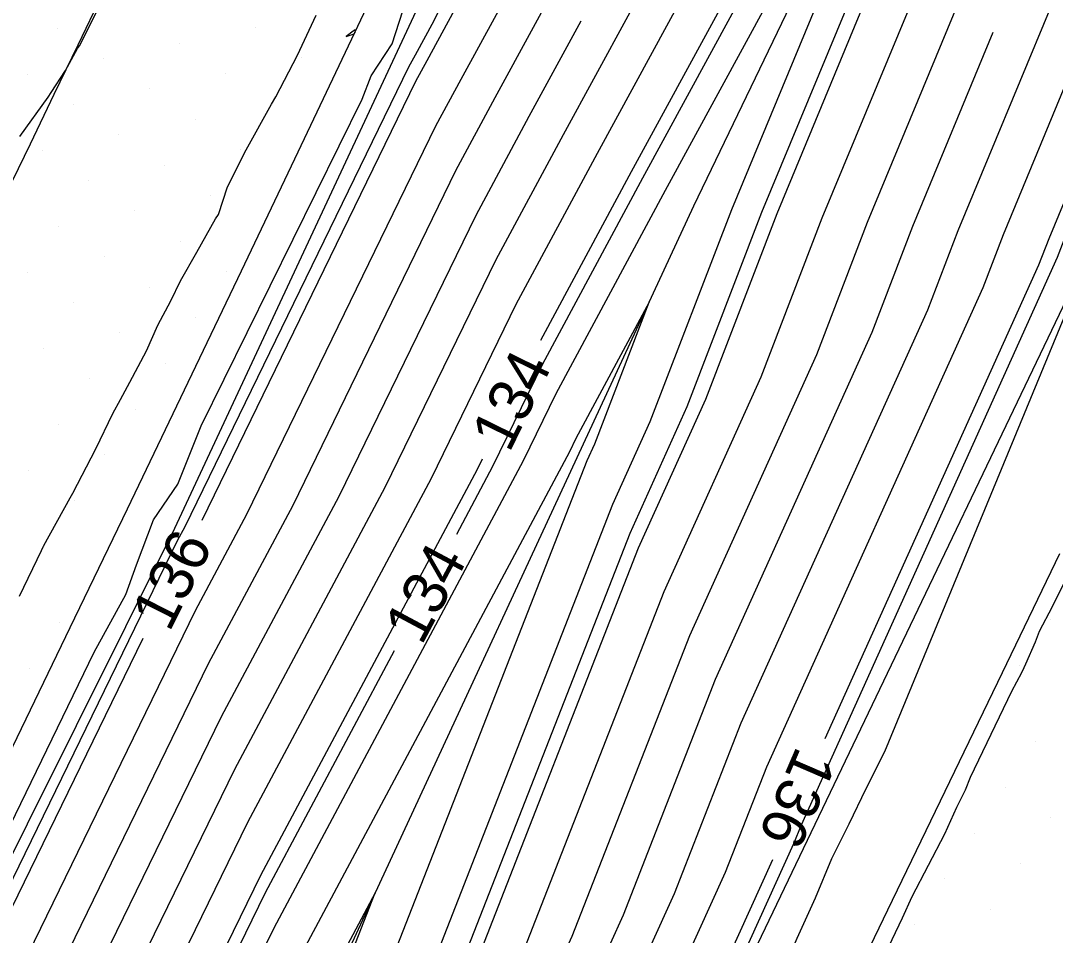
# Model space of a CAD drawing. Extents: x 2354170 to 2357230, y 866100 to 868290.
# Drawn here: x 2355291.7 to 2355338.78, y 866319.23 to 866360.82 of the extents above; entities that cross this region are included whole.
import ezdxf

# ---------------------------------------------------------------- set-up
doc = ezdxf.new("R2010")
doc.units = 0
for name, color, linetype in [('Default', 7, 'Continuous'), ('DTM Contours Major', 7, 'Continuous'), ('DTM Contours Minor', 7, 'Continuous'), ('DTM Contours Minor Text', 7, 'Continuous'), ('Exist DTM Breakline', 7, 'Continuous'), ('Exist DTM Scan Elevation Point', 7, 'Continuous'), ('Exist Roads EOP', 7, 'Continuous'), ('PH Exist DTM Breakline', 7, 'Continuous')]:
    doc.layers.add(name, color=color, linetype=linetype)

msp = doc.modelspace()

# ---------------------------------------------------------------- linework, layer by layer
at = {"layer": 'Default'}
for points in [[(2355362.019, 866434.7), (2355360.618, 866431.85), (2355360.1, 866430.777), (2355354.214, 866419.388), (2355353.064, 866417.142), (2355340.439, 866392.713), (2355339.805, 866391.476), (2355333.667, 866380.332), (2355331.988, 866376.904), (2355319.48, 866353.942), (2355315.349, 866346.27)], [(2355344.863, 866427.426), (2355333.508, 866405.265), (2355331.367, 866401.122), (2355324.415, 866387.55), (2355323.476, 866385.846), (2355311.639, 866361.675), (2355310.176, 866358.99), (2355309.668, 866358.047), (2355299.946, 866338.09)], [(2355346.547, 866426.331), (2355336.768, 866407.245), (2355332.879, 866399.721), (2355326.98, 866388.205), (2355325.175, 866384.927), (2355315.03, 866364.214), (2355311.726, 866358.149), (2355310.58, 866356.02), (2355301.98, 866338.364), (2355299.636, 866333.974), (2355288.647, 866311.443), (2355286.904, 866307.449), (2355279.659, 866292.572), (2355279.343, 866291.067), (2355277.379, 866286.427), (2355269.582, 866267.361)], [(2355370.996, 866418.563), (2355366.551, 866409.441), (2355365.482, 866407.418), (2355364.469, 866405.339), (2355362.138, 866400.926), (2355351.253, 866378.232), (2355350.488, 866376.361), (2355339.875, 866354.269), (2355338.477, 866350.901), (2355338.018, 866349.707), (2355328.291, 866328.165)], [(2355346.545, 866413.183), (2355337.415, 866395.516), (2355334.675, 866390.167), (2355330.27, 866382.17), (2355325.205, 866371.828), (2355316.378, 866355.625), (2355313.316, 866349.936), (2355308.274, 866339.587), (2355301.426, 866326.76), (2355294.428, 866312.41), (2355289.665, 866301.5), (2355285.05, 866292.025), (2355284.22, 866288.074), (2355279.066, 866275.895)], [(2355340.027, 866409.224), (2355334.391, 866398.319), (2355329.545, 866388.859), (2355326.873, 866384.008), (2355318.422, 866366.752), (2355313.277, 866357.307), (2355311.492, 866353.992), (2355304.078, 866338.772), (2355300.233, 866331.569), (2355290.574, 866311.765), (2355287.824, 866305.466), (2355281.456, 866292.39), (2355280.968, 866290.07), (2355277.941, 866282.916), (2355271.317, 866266.718)], [(2355338.927, 866394.115), (2355337.24, 866390.821), (2355331.969, 866381.251), (2355328.597, 866374.366), (2355317.929, 866354.783), (2355314.227, 866347.909), (2355310.373, 866339.995), (2355302.023, 866324.355), (2355296.354, 866312.732), (2355290.585, 866299.517), (2355286.848, 866291.842), (2355285.846, 866287.077), (2355279.628, 866272.384)], [(2355307.474, 866311.114), (2355309.825, 866316.293), (2355318.648, 866338.833), (2355320.345, 866342.59), (2355324.053, 866352.236), (2355335.221, 866379.152), (2355321.03, 866353.1), (2355316.051, 866343.853), (2355314.569, 866340.81), (2355303.217, 866319.546), (2355300.208, 866313.377), (2355292.425, 866295.55), (2355290.442, 866291.477), (2355289.097, 866285.082), (2355280.753, 866265.362)], [(2355295.93, 866277.918), (2355297.289, 866281.095), (2355299.682, 866284.596), (2355304.457, 866295.671), (2355310.044, 866308.469), (2355314.474, 866318.226), (2355320.982, 866334.853), (2355325.394, 866344.623), (2355328.175, 866351.855), (2355336.64, 866372.256), (2355339.663, 866378.549)], [(2355297.265, 866276.227), (2355299.022, 866280.337), (2355300.896, 866283.079), (2355306.792, 866296.752), (2355311.329, 866307.146), (2355316.798, 866319.192), (2355322.15, 866332.863), (2355327.919, 866345.64), (2355330.235, 866351.664), (2355337.287, 866368.659), (2355341.828, 866378.112)], [(2355299.933, 866272.846), (2355302.488, 866278.82), (2355303.324, 866280.044), (2355311.461, 866298.914), (2355313.9, 866304.5), (2355321.447, 866321.125), (2355324.484, 866328.882), (2355332.969, 866347.673), (2355334.356, 866351.282), (2355338.581, 866361.464), (2355346.158, 866377.236)], [(2355291.94, 866275.064), (2355294.596, 866279.608), (2355295.556, 866281.853), (2355298.468, 866286.114), (2355302.123, 866294.59), (2355308.759, 866309.791), (2355312.149, 866317.259), (2355319.815, 866336.843), (2355322.869, 866343.607), (2355326.114, 866352.046), (2355332.101, 866366.476)], [(2355291.664, 866355.545), (2355292.951, 866357.342), (2355293.092, 866357.551), (2355293.741, 866358.553), (2355294.287, 866359.562), (2355294.374, 866359.67), (2355295.392, 866361.693)], [(2355266.111, 866268.646), (2355275.282, 866291.07), (2355274.685, 866290.143), (2355275.184, 866291.11), (2355275.57, 866291.874), (2355275.855, 866292.514), (2355276.2, 866293.354), (2355276.747, 866294.675), (2355282.939, 866307.557), (2355283.875, 866309.403), (2355284.665, 866311.146), (2355285.537, 866312.659), (2355286.204, 866313.902), (2355295.041, 866332.108), (2355296.478, 866334.729), (2355296.966, 866336.075), (2355297.748, 866338.127), (2355298.85, 866339.748), (2355299.916, 866342.394), (2355307.241, 866357.243), (2355307.65, 866358.314), (2355308.598, 866359.764), (2355309.085, 866361.27)], [(2355317.189, 866360.801), (2355314.828, 866356.466), (2355312.404, 866351.964), (2355306.176, 866339.18), (2355300.829, 866329.165), (2355292.501, 866312.087), (2355288.744, 866303.483), (2355283.253, 866292.207), (2355282.594, 866289.072), (2355278.504, 866279.405), (2355274.815, 866270.385)], [(2355291.64, 866334.652), (2355292.651, 866336.721), (2355292.73, 866336.893), (2355292.744, 866336.919), (2355292.76, 866336.951), (2355293.956, 866339.114), (2355294.08, 866339.329), (2355295.117, 866341.344), (2355295.899, 866342.95), (2355296.24, 866343.598), (2355296.66, 866344.378), (2355297.427, 866345.811), (2355297.945, 866346.975), (2355298.537, 866348.074), (2355298.973, 866348.989), (2355299.722, 866350.288), (2355300.558, 866351.81), (2355300.697, 866352.008), (2355301.117, 866353.261), (2355301.965, 866354.951), (2355303.114, 866357.021), (2355303.307, 866357.358), (2355304.299, 866359.25), (2355305.15, 866361.071)], [(2355295.371, 866269.014), (2355298.599, 866274.537), (2355300.755, 866279.578), (2355302.11, 866281.561), (2355309.127, 866297.833), (2355312.615, 866305.823), (2355319.123, 866320.158), (2355323.317, 866330.872), (2355330.444, 866346.657), (2355332.296, 866351.473), (2355335.956, 866360.295)], [(2355306.914, 866360.278), (2355306.938, 866360.351), (2355306.918, 866360.404), (2355306.836, 866360.342), (2355306.514, 866360.095), (2355306.874, 866360.216), (2355306.914, 866360.278)], [(2355304.221, 866278.062), (2355304.538, 866278.526), (2355313.796, 866299.995), (2355315.185, 866303.177), (2355323.771, 866322.091), (2355325.651, 866326.892), (2355335.494, 866348.69), (2355336.417, 866351.091), (2355339.228, 866357.866)], [(2355340.495, 866350.531), (2355331.001, 866327.562), (2355330.154, 866325.881), (2355329.384, 866324.284), (2355328.592, 866322.7), (2355327.857, 866320.914), (2355327.02, 866319.083), (2355321.074, 866305.192), (2355319.633, 866302.589), (2355318.634, 866300.202), (2355317.41, 866297.966), (2355316.183, 866294.558), (2355312.238, 866284.632), (2355310.002, 866280.655), (2355308.5, 866277.295)], [(2355306.189, 866312.437), (2355307.5, 866315.326), (2355317.481, 866340.824), (2355317.82, 866341.573), (2355320.298, 866348.019), (2355316.963, 866341.825), (2355316.667, 866341.218), (2355303.813, 866317.142), (2355302.135, 866313.7), (2355293.346, 866293.567), (2355292.239, 866291.295), (2355290.723, 866284.084), (2355285.885, 866272.65), (2355291.928, 866282.99), (2355292.09, 866283.369), (2355296.039, 866289.149), (2355297.454, 866292.429), (2355306.189, 866312.437)], [(2355312.705, 866340.884), (2355312.471, 866340.403), (2355302.62, 866321.951), (2355298.281, 866313.055), (2355291.505, 866297.534), (2355288.645, 866291.66), (2355287.471, 866286.079), (2355280.19, 866268.873), (2355278.258, 866264.148), (2355277.348, 866261.759), (2355277.04, 866261.671), (2355276.558, 866260.821), (2355276.155, 866259.945), (2355272.434, 866249.729)], [(2355339.561, 866336.02), (2355338.626, 866334.158), (2355338.048, 866333.043), (2355337.855, 866332.552), (2355337.427, 866331.563), (2355337.347, 866331.39), (2355337.236, 866331.162), (2355336.776, 866330.308), (2355334.9, 866326.402), (2355334.67, 866325.831), (2355334.278, 866325.032), (2355333.741, 866323.82), (2355332.249, 866320.974), (2355331.815, 866319.997), (2355331.018, 866318.346)], [(2355297.258, 866332.727), (2355286.72, 866311.12), (2355285.984, 866309.432), (2355277.862, 866292.755), (2355277.717, 866292.065), (2355276.817, 866289.938), (2355267.847, 866268.003), (2355267.559, 866267.247), (2355266.03, 866266.809), (2355263.633, 866262.589), (2355261.636, 866258.24), (2355259.392, 866252.08), (2355257.363, 866247.97), (2355255.249, 866243.896), (2355254.805, 866242.902)], [(2355325.915, 866322.658), (2355316.47, 866301.854), (2355316.131, 866301.076), (2355311.613, 866290.599), (2355307.228, 866279.568), (2355306.602, 866278.454), (2355306.182, 866277.514), (2355305.692, 866276.594), (2355305.248, 866275.652), (2355302.601, 866269.465), (2355300.389, 866265.68), (2355298.499, 866261.311), (2355296.219, 866256.981), (2355295.908, 866256.462), (2355293.954, 866252.056), (2355291.877, 866247.68), (2355289.746, 866243.4), (2355286.357, 866237.869), (2355284.634, 866233.7), (2355283.785, 866232.093)], [(2355307.833, 866321.149), (2355304.41, 866314.737), (2355304.062, 866314.022), (2355294.266, 866291.584), (2355294.036, 866291.112), (2355293.55, 866288.8), (2355294.825, 866290.667), (2355295.119, 866291.348), (2355304.903, 866313.76), (2355305.176, 866314.36), (2355307.833, 866321.149)]]:
    msp.add_lwpolyline(points, dxfattribs=at)
at = {"layer": 'DTM Contours Major'}
for points in [[(2355317.189, 866360.801), (2355314.828, 866356.466), (2355312.404, 866351.964), (2355306.176, 866339.18), (2355300.829, 866329.165), (2355292.501, 866312.087), (2355288.744, 866303.483), (2355283.253, 866292.207), (2355282.594, 866289.072), (2355278.504, 866279.405), (2355274.815, 866270.385)], [(2355295.371, 866269.014), (2355298.599, 866274.537), (2355300.755, 866279.578), (2355302.11, 866281.561), (2355309.127, 866297.833), (2355312.615, 866305.823), (2355319.123, 866320.158), (2355323.317, 866330.872), (2355330.444, 866346.657), (2355332.296, 866351.473), (2355335.956, 866360.295)]]:
    msp.add_lwpolyline(points, dxfattribs=at)
at = {"layer": 'DTM Contours Minor'}
for points in [[(2355399.763, 866516.766), (2355393.392, 866501.457), (2355392.787, 866500.397), (2355391.502, 866497.306), (2355381.19, 866472.262), (2355380.988, 866471.775), (2355374.355, 866458.281), (2355373.867, 866457.271), (2355361.144, 866431.383), (2355360.874, 866430.823), (2355354.726, 866418.925), (2355354.15, 866417.801), (2355340.943, 866392.246), (2355340.66, 866391.694), (2355334.233, 866380.026), (2355333.119, 866377.75), (2355319.997, 866353.661), (2355315.443, 866345.205), (2355313.17, 866340.539), (2355311.526, 866337.459)], [(2355407.018, 866492.981), (2355404.637, 866487.713), (2355403.129, 866484.793), (2355392.216, 866460.604), (2355391.559, 866459.237), (2355379.811, 866435.133), (2355378.381, 866432.158), (2355366.791, 866408.374), (2355365.995, 866406.866), (2355364.93, 866404.683), (2355363.188, 866401.383), (2355351.753, 866377.544), (2355351.21, 866376.215), (2355340.091, 866353.07), (2355339.164, 866350.837), (2355338.86, 866350.045), (2355327.207, 866324.238), (2355326.871, 866323.38), (2355321.752, 866312.104)], [(2355308.331, 866310.232), (2355311.374, 866316.937), (2355319.426, 866337.506), (2355322.028, 866343.268), (2355325.427, 866352.109), (2355335.777, 866377.053), (2355336.776, 866379.133), (2355341.753, 866391.314), (2355342.196, 866392.238), (2355355.699, 866417.805), (2355355.75, 866417.909), (2355361.981, 866429.708), (2355362.581, 866430.939), (2355375.051, 866456.87), (2355375.559, 866457.912), (2355382.058, 866471.427), (2355382.481, 866472.365), (2355392.371, 866491.519)], [(2355267.268, 866268.217), (2355276.63, 866291.108), (2355277.175, 866292.398), (2355277.263, 866292.816), (2355285.677, 866310.094), (2355286.078, 866311.013), (2355298.84, 866337.18), (2355299.182, 866337.821), (2355309.364, 866358.723), (2355309.659, 866359.271), (2355310.508, 866360.829), (2355322.91, 866386.152), (2355323.56, 866387.332), (2355330.863, 866401.589), (2355332.422, 866404.606), (2355337.089, 866413.714)], [(2355308.7, 866332.166), (2355302.819, 866321.149), (2355298.923, 866313.162), (2355291.812, 866296.872), (2355289.244, 866291.599), (2355288.013, 866285.747), (2355280.378, 866267.702)]]:
    msp.add_lwpolyline(points, dxfattribs=at)
at = {"layer": 'Exist DTM Breakline'}
msp.add_lwpolyline([(2355295.385, 866361.961), (2355294.298, 866359.709), (2355293.212, 866357.458), (2355292.126, 866355.206), (2355291.04, 866352.954), (2355289.954, 866350.702), (2355288.868, 866348.45), (2355287.786, 866346.197), (2355286.707, 866343.942), (2355285.627, 866341.687), (2355284.547, 866339.432), (2355283.466, 866337.178), (2355282.385, 866334.924), (2355281.304, 866332.67), (2355280.223, 866330.415), (2355279.139, 866328.162), (2355278.055, 866325.91), (2355276.97, 866323.658), (2355275.885, 866321.405), (2355274.801, 866319.153)], dxfattribs=at)
at = {"layer": 'Exist DTM Scan Elevation Point'}
for p, q in [((2355293.381, 866360.478), (2355293.381, 866360.478)), ((2355302.395, 866360.51), (2355302.395, 866360.51)), ((2355298.93, 866359.804), (2355298.93, 866359.804)), ((2355295.466, 866359.099), (2355295.466, 866359.099)), ((2355304.48, 866359.13), (2355304.48, 866359.13)), ((2355292.001, 866358.393), (2355292.001, 866358.393)), ((2355301.015, 866358.425), (2355301.015, 866358.425)), ((2355297.551, 866357.719), (2355297.551, 866357.719)), ((2355294.086, 866357.014), (2355294.086, 866357.014)), ((2355303.1, 866357.045), (2355303.1, 866357.045)), ((2355299.636, 866356.34), (2355299.636, 866356.34)), ((2355296.171, 866355.634), (2355296.171, 866355.634)), ((2355292.707, 866354.929), (2355292.707, 866354.929)), ((2355301.721, 866354.96), (2355301.721, 866354.96)), ((2355298.256, 866354.255), (2355298.256, 866354.255)), ((2355294.792, 866353.549), (2355294.792, 866353.549)), ((2355300.341, 866352.875), (2355300.341, 866352.875)), ((2355296.877, 866352.17), (2355296.877, 866352.17)), ((2355293.413, 866351.464), (2355293.413, 866351.464)), ((2355298.962, 866350.79), (2355298.962, 866350.79)), ((2355295.498, 866350.085), (2355295.498, 866350.085)), ((2355292.033, 866349.379), (2355292.033, 866349.379)), ((2355301.047, 866349.411), (2355301.047, 866349.411)), ((2355297.583, 866348.705), (2355297.583, 866348.705)), ((2355294.118, 866348), (2355294.118, 866348)), ((2355299.668, 866347.326), (2355299.668, 866347.326)), ((2355296.203, 866346.62), (2355296.203, 866346.62)), ((2355292.739, 866345.915), (2355292.739, 866345.915)), ((2355298.288, 866345.241), (2355298.288, 866345.241)), ((2355294.824, 866344.535), (2355294.824, 866344.535)), ((2355296.909, 866343.156), (2355296.909, 866343.156)), ((2355293.444, 866342.45), (2355293.444, 866342.45)), ((2355295.529, 866341.071), (2355295.529, 866341.071)), ((2355292.065, 866340.366), (2355292.065, 866340.366)), ((2355294.15, 866338.986), (2355294.15, 866338.986)), ((2355292.77, 866336.901), (2355292.77, 866336.901)), ((2355293.476, 866333.437), (2355293.476, 866333.437)), ((2355338.545, 866333.595), (2355338.545, 866333.595)), ((2355337.166, 866331.51), (2355337.166, 866331.51)), ((2355292.097, 866331.352), (2355292.097, 866331.352)), ((2355337.871, 866328.046), (2355337.871, 866328.046)), ((2355336.492, 866325.961), (2355336.492, 866325.961)), ((2355338.577, 866324.581), (2355338.577, 866324.581)), ((2355335.112, 866323.876), (2355335.112, 866323.876)), ((2355337.197, 866322.496), (2355337.197, 866322.496)), ((2355333.733, 866321.791), (2355333.733, 866321.791)), ((2355335.818, 866320.411), (2355335.818, 866320.411)), ((2355332.353, 866319.706), (2355332.353, 866319.706))]:
    msp.add_line(p, q, dxfattribs=at)
at = {"layer": 'Exist Roads EOP'}
for points in [[(2355264.972, 866273.924), (2355267.599, 866279.318), (2355270.234, 866284.708), (2355272.877, 866290.095), (2355275.523, 866295.48), (2355278.171, 866300.864), (2355280.817, 866306.249), (2355283.459, 866311.636), (2355286.096, 866317.026), (2355288.725, 866322.419), (2355291.347, 866327.816), (2355293.96, 866333.217), (2355296.564, 866338.622), (2355299.16, 866344.032), (2355301.748, 866349.445), (2355304.329, 866354.861), (2355306.905, 866360.281), (2355309.475, 866365.702)], [(2355338.974, 866336.568), (2355336.36, 866331.167), (2355333.748, 866325.765), (2355331.139, 866320.362), (2355328.532, 866314.958), (2355325.926, 866309.554), (2355323.32, 866304.149), (2355320.716, 866298.744), (2355318.111, 866293.339), (2355315.505, 866287.934), (2355312.899, 866282.53), (2355310.294, 866277.125)]]:
    msp.add_lwpolyline(points, dxfattribs=at)
at = {"layer": 'PH Exist DTM Breakline'}
for points in [[(2355462.264, 866681.282), (2355449.29, 866652.845), (2355431.772, 866616.884), (2355416.85, 866585.734), (2355398.908, 866547.275), (2355381.513, 866510.255), (2355362.049, 866469.228), (2355342.769, 866429.753), (2355321.636, 866386.842), (2355298.704, 866337.728), (2355276.341, 866292.909), (2355263.024, 866269.789)], [(2355493.481, 866667.653), (2355482.335, 866644.759), (2355460.278, 866598.533), (2355441.015, 866560.468), (2355418.38, 866513.657), (2355393.36, 866459.386), (2355366.298, 866402.738), (2355340.515, 866350.712), (2355316.886, 866301.426), (2355305.28, 866277.599)], [(2355281.117, 866263.09), (2355291.385, 866283.678), (2355294.507, 866291.064), (2355304.567, 866314.107), (2355322.328, 866352.396), (2355341.35, 866391.869), (2355361.718, 866430.873), (2355381.648, 866471.864), (2355403.329, 866518.372), (2355424.612, 866562.24), (2355423.403, 866563.319), (2355423.174, 866564.881), (2355424.474, 866567.914), (2355426.326, 866567.421), (2355427.666, 866565.955), (2355427.962, 866564.005), (2355426.4, 866561.553)]]:
    msp.add_lwpolyline(points, dxfattribs=at)

# ---------------------------------------------------------------- texts
at = {"layer": 'Default'}
for s, rotation, p in [('134', 63.857, (2355313.928, 866341.126)), ('136', 63.3763, (2355298.461, 866332.969)), ('136', 246.655, (2355327.028, 866327.887))]:
    msp.add_text(s, height=2, rotation=rotation, dxfattribs=at).set_placement(p)
at = {"layer": 'DTM Contours Minor Text'}
msp.add_text('134', height=2, rotation=61.9035, dxfattribs=at).set_placement((2355309.938, 866332.362))

doc.saveas('drawing.dxf')
